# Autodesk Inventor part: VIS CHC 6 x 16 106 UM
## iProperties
Shininess: 20.0
Angle Display Precision: 2
Document Length Units: 11269
Document Angle Units: 11279
Document Time Units: 11290
Document Mass Units: 11283
Document Length Units Precision: 3
Document Angle Units Precision: 2
Created: 2002-02
Part Number: VIS CHC 6 x 16 106 UM
Material: Par défaut
Catalog Web Link: www.traceparts.com
Description: Vis tête cylindrique a 6 pans creux
Vendor: RABOURDIN
Document SubType Name: Modélisation
Standard: 527 - 6 x 16
Designer: Administrateur
Density: 0.0
Volumn: 0.0
Area: 0.0
PropertySet Name: Model Information
Control State: 0
Master: False
Checked Out: False
Author: Administrateur
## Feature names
1. Base1
